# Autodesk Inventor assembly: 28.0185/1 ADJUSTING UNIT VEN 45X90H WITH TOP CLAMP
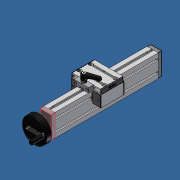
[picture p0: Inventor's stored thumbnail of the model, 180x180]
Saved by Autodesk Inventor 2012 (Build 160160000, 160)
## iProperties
Created: 2007-06
Part Number: 28.0185/1 ADJUSTING UNIT VEN 45X90H WITH TOP CLAMP
Document SubType Name: Assembly
Designer: Andy Moles
Author: Andy Moles
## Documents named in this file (21)
- C:\Andys Backup Data\ANDY'S INVENTOR\INVENTOR LIBRARIES\PARTS LIBRARY\READY FOR USE MODULES LG\28.0185_1 ADJUSTING UNIT VEN 45X90H WITH TOP CLAMP.iam
- C:\Andys Backup Data\ANDY'S INVENTOR\INVENTOR LIBRARIES\PARTS LIBRARY\READY FOR USE MODULES LG\SUBCOMPONENTS\50.1264 BALL BEARING 10X30X9 6200 2RS DIN 625.ipt
- C:\Andys Backup Data\ANDY'S INVENTOR\INVENTOR LIBRARIES\PARTS LIBRARY\READY FOR USE MODULES LG\SUBCOMPONENTS\28.0201 BEARING PLATE 45X90 IDLER SIDE.ipt
- C:\Andys Backup Data\ANDY'S INVENTOR\INVENTOR LIBRARIES\PARTS LIBRARY\READY FOR USE MODULES LG\SUBCOMPONENTS\28.0200 BEARING PLATE 45X90 HANDWHEEL SIDE.ipt
- C:\Andys Backup Data\ANDY'S INVENTOR\INVENTOR LIBRARIES\PARTS LIBRARY\READY FOR USE MODULES LG\SUBCOMPONENTS\28.0204 HANDWHEEL 100mm.iam
- C:\Andys Backup Data\ANDY'S INVENTOR\INVENTOR LIBRARIES\PARTS LIBRARY\FASTENING ELEMENTS\NUTS\21.1351 M8 SQUARE NUT.ipt
- C:\Andys Backup Data\ANDY'S INVENTOR\INVENTOR LIBRARIES\PARTS LIBRARY\FASTENING ELEMENTS\SCREWS CAP\21.1204 M8X25.ipt
- C:\Andys Backup Data\ANDY'S INVENTOR\INVENTOR LIBRARIES\PARTS LIBRARY\READY FOR USE MODULES LG\SUBCOMPONENTS\28.0221_1 ACME SCREW 16X4 TOP LOCK.ipt
- C:\Andys Backup Data\ANDY'S INVENTOR\INVENTOR LIBRARIES\PARTS LIBRARY\FASTENING ELEMENTS\WASHERS\21.1326 DISC SPRING 20.ipt
- C:\Andys Backup Data\ANDY'S INVENTOR\INVENTOR LIBRARIES\PARTS LIBRARY\READY FOR USE MODULES LG\SUBCOMPONENTS\28.0214_3 RAIL 45X90 H PROFILE TOP LOCK.ipt
- C:\Andys Backup Data\ANDY'S INVENTOR\INVENTOR LIBRARIES\PARTS LIBRARY\READY FOR USE MODULES LG\SUBCOMPONENTS\28.0222_1 LWN 32X45-45 90X19-NSC.ipt
- 28.0222/1 SLIDE LWN 32X45-45 90X19.ipt
- C:\Andys Backup Data\ANDY'S INVENTOR\INVENTOR LIBRARIES\PARTS LIBRARY\READY FOR USE MODULES LG\SUBCOMPONENTS\28.0126 SLIDE 45X32.ipt
- C:\Andys Backup Data\ANDY'S INVENTOR\INVENTOR LIBRARIES\PARTS LIBRARY\READY FOR USE MODULES LG\SUBCOMPONENTS\28.0256 Nut slide connector 38.5.ipt
- C:\Andys Backup Data\ANDY'S INVENTOR\INVENTOR LIBRARIES\PARTS LIBRARY\FASTENING ELEMENTS\SCREWS CAP\21.1200 M8X16.ipt
- C:\Andys Backup Data\ANDY'S INVENTOR\INVENTOR LIBRARIES\PARTS LIBRARY\FASTENING ELEMENTS\SCREWS CAP\21.1235 M5X16.ipt
- C:\Andys Backup Data\ANDY'S INVENTOR\INVENTOR LIBRARIES\PARTS LIBRARY\COMPONENTS LR\28.0270_9 SLIDE CLAMPING UNIT 5mm OFFSET..iam
- C:\Andys Backup Data\ANDY'S INVENTOR\INVENTOR LIBRARIES\PARTS LIBRARY\COMPONENTS LG\22.1095 SLIDE RAIL LN.iam
- C:\Andys Backup Data\ANDY'S INVENTOR\INVENTOR LIBRARIES\PARTS LIBRARY\END CAPS\22.1003_1 END CAP 45x32 Z Gray.iam
- C:\Andys Backup Data\ANDY'S INVENTOR\INVENTOR LIBRARIES\PARTS LIBRARY\END CAPS\22.1014_1 END CAP 90X19 GRAY.ipt
- C:\Andys Backup Data\ANDY'S INVENTOR\INVENTOR LIBRARIES\PARTS LIBRARY\READY FOR USE MODULES LG\SUBCOMPONENTS\28.0257 BRONZE NUT 16X4 NOTCHED.ipt
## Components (37 placed, 19 different names)
1. 28.0214_3 RAIL 45X90 H PROFILE TOP LOCK:1 — Mate:1, Flush:1, Mate:2, Mate:6, Angle:3, Flush:3, Mate:21, Flush:4, Flush:5, Flush:6, Flush:7, Angle:16, Mate:38, Mate:39
2. 50.1264 10X30X9 6200 2RS DIN 625 BALL BEARING:1 — Insert:10, Insert:13
3. 50.1264 10X30X9 6200 2RS DIN 625 BALL BEARING:2 — Insert:9
4. 28.0201 BEARING PLATE 45X90 IDLER SIDE:1 — Mate:6, Insert:7, Insert:8, Insert:9, Angle:3, Flush:6, Flush:7
5. 28.0200 BEARING PLATE 45X90 HANDWHEEL SIDE:1 — Insert:3, Insert:5, Insert:6, Insert:10, Flush:3, Mate:21, Flush:4, Flush:5, Angle:6, Angle:18
6. 28.0204 HANDWHEEL 100mm:1 [sub-assembly] — Insert:3, Angle:5, Angle:6
7. 21.1204  M8 x 25:1 — Insert:5
8. 21.1204  M8 x 25:2 — Insert:6
9. 21.1204  M8 x 25:3 — Insert:7
10. 21.1204  M8 x 25:4 — Insert:8
11. 28.0221_1 ACME SCREW 16X4 TOP LOCK:1 — Insert:11, Insert:12, Angle:5, Mate:36
12. 21.1326 DISC SPRING 20:1 — Insert:11, Insert:13
13. 21.1326 DISC SPRING 20:2 — Insert:12
14. 28.0222\1 SLIDE LWN 32X45-45 90X19:1 — Insert:14, Insert:15, Insert:16, Insert:17, Insert:18, Insert:19, Insert:20, Insert:21, Insert:22, Insert:23, Angle:7, Angle:8, Angle:9, Angle:10, Insert:24, Angle:11, Mate:26, Flush:8, Mate:27, Flush:9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
15. 28.0126 SLIDE 45X32:1 — Mate:27, Flush:9, Flush:10, Mate:30, Flush:13, Mate:31, Insert:25, Insert:28, Angle:13, Angle:17
16. 28.0126 SLIDE 45X32:2 — Mate:26, Flush:8, Flush:11, Mate:32, Flush:14, Mate:33, Insert:26, Insert:27, Angle:14, Angle:15
17. 28.0256 Nut slide connector 38.5:1 — Insert:24, Angle:11, Mate:37, Mate:40
18. 21.1200 M8 x 16:1 — Insert:16
19. 21.1200 M8 x 16:2 — Insert:17
20. 21.1200 M8 x 16:3 — Insert:18
21. 21.1200 M8 x 16:4 — Insert:19
22. 21.1235  M5 x 16:1 — Insert:15
23. 21.1235  M5 x 16:2 — Insert:14
24. 21.1351 M8 SQUARE NUT:2 — Insert:21, Angle:10
25. 21.1351 M8 SQUARE NUT:3 — Insert:22, Angle:7
26. 21.1351 M8 SQUARE NUT:4 — Insert:23, Angle:8
27. 21.1351 M8 SQUARE NUT:5 — Insert:20, Angle:9
28. 28.0270_9 SLIDE CLAMPING UNIT 5mm OFFSET.:1 [sub-assembly] — Mate:28, Angle:12, Flush:12, Mate:29
29. 22.1095 SLIDE RAIL LN:1 [sub-assembly] — Mate:30, Flush:13, Mate:31
30. 22.1095 SLIDE RAIL LN:2 [sub-assembly] — Mate:32, Flush:14, Mate:33, Mate:38, Mate:39
31. 22.1003\1 END CAP 45x32 Z Gray:1 [sub-assembly] — Insert:25, Angle:17
32. 22.1003\1 END CAP 45x32 Z Gray:2 [sub-assembly] — Insert:26, Angle:15
33. 22.1003\1 END CAP 45x32 Z Gray:3 [sub-assembly] — Insert:27, Angle:14
34. 22.1003\1 END CAP 45x32 Z Gray:4 [sub-assembly] — Insert:28, Angle:13
35. 22.1014_1 END CAP 90X19 GRAY:1 — Mate:34, Flush:15, Flush:16
36. 22.1014_1 END CAP 90X19 GRAY:2 — Mate:35, Flush:17, Flush:18
37. 28.0257 BRONZE NUT 16X4 NOTCHED:1 — Mate:36, Mate:37, Mate:40
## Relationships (76: Insert 25, Mate 19, Flush 17, Angle 15)
- Mate:1: 28.0214_3 RAIL 45X90 H PROFILE TOP LOCK:1
- Flush:1: 28.0214_3 RAIL 45X90 H PROFILE TOP LOCK:1
- Mate:2: 28.0214_3 RAIL 45X90 H PROFILE TOP LOCK:1
- Mate:6: 28.0214_3 RAIL 45X90 H PROFILE TOP LOCK:1 ↔ 28.0201 BEARING PLATE 45X90 IDLER SIDE:1
- Insert:3: 28.0200 BEARING PLATE 45X90 HANDWHEEL SIDE:1 ↔ 28.0204 HANDWHEEL 100mm:1
- Insert:5: 28.0200 BEARING PLATE 45X90 HANDWHEEL SIDE:1 ↔ 21.1204  M8 x 25:1
- Insert:6: 28.0200 BEARING PLATE 45X90 HANDWHEEL SIDE:1 ↔ 21.1204  M8 x 25:2
- Insert:7: 28.0201 BEARING PLATE 45X90 IDLER SIDE:1 ↔ 21.1204  M8 x 25:3
- Insert:8: 28.0201 BEARING PLATE 45X90 IDLER SIDE:1 ↔ 21.1204  M8 x 25:4
- Insert:9: 50.1264 10X30X9 6200 2RS DIN 625 BALL BEARING:2 ↔ 28.0201 BEARING PLATE 45X90 IDLER SIDE:1
- Insert:10: 50.1264 10X30X9 6200 2RS DIN 625 BALL BEARING:1 ↔ 28.0200 BEARING PLATE 45X90 HANDWHEEL SIDE:1
- Angle:3: 28.0214_3 RAIL 45X90 H PROFILE TOP LOCK:1 ↔ 28.0201 BEARING PLATE 45X90 IDLER SIDE:1
- Flush:3: 28.0214_3 RAIL 45X90 H PROFILE TOP LOCK:1 ↔ 28.0200 BEARING PLATE 45X90 HANDWHEEL SIDE:1
- Mate:21: 28.0214_3 RAIL 45X90 H PROFILE TOP LOCK:1 ↔ 28.0200 BEARING PLATE 45X90 HANDWHEEL SIDE:1
- Flush:4: 28.0214_3 RAIL 45X90 H PROFILE TOP LOCK:1 ↔ 28.0200 BEARING PLATE 45X90 HANDWHEEL SIDE:1
- Flush:5: 28.0214_3 RAIL 45X90 H PROFILE TOP LOCK:1 ↔ 28.0200 BEARING PLATE 45X90 HANDWHEEL SIDE:1
- Flush:6: 28.0214_3 RAIL 45X90 H PROFILE TOP LOCK:1 ↔ 28.0201 BEARING PLATE 45X90 IDLER SIDE:1
- Flush:7: 28.0214_3 RAIL 45X90 H PROFILE TOP LOCK:1 ↔ 28.0201 BEARING PLATE 45X90 IDLER SIDE:1
- Insert:11: 28.0221_1 ACME SCREW 16X4 TOP LOCK:1 ↔ 21.1326 DISC SPRING 20:1
- Insert:12: 28.0221_1 ACME SCREW 16X4 TOP LOCK:1 ↔ 21.1326 DISC SPRING 20:2
- Insert:13: 50.1264 10X30X9 6200 2RS DIN 625 BALL BEARING:1 ↔ 21.1326 DISC SPRING 20:1
- Angle:5: 28.0204 HANDWHEEL 100mm:1 ↔ 28.0221_1 ACME SCREW 16X4 TOP LOCK:1
- Angle:6: 28.0200 BEARING PLATE 45X90 HANDWHEEL SIDE:1 ↔ 28.0204 HANDWHEEL 100mm:1
- Insert:14: 28.0222\1 SLIDE LWN 32X45-45 90X19:1 ↔ 21.1235  M5 x 16:2
- Insert:15: 28.0222\1 SLIDE LWN 32X45-45 90X19:1 ↔ 21.1235  M5 x 16:1
- Insert:16: 28.0222\1 SLIDE LWN 32X45-45 90X19:1 ↔ 21.1200 M8 x 16:1
- Insert:17: 28.0222\1 SLIDE LWN 32X45-45 90X19:1 ↔ 21.1200 M8 x 16:2
- Insert:18: 28.0222\1 SLIDE LWN 32X45-45 90X19:1 ↔ 21.1200 M8 x 16:3
- Insert:19: 28.0222\1 SLIDE LWN 32X45-45 90X19:1 ↔ 21.1200 M8 x 16:4
- Insert:20: 28.0222\1 SLIDE LWN 32X45-45 90X19:1 ↔ 21.1351 M8 SQUARE NUT:5
- Insert:21: 28.0222\1 SLIDE LWN 32X45-45 90X19:1 ↔ 21.1351 M8 SQUARE NUT:2
- Insert:22: 28.0222\1 SLIDE LWN 32X45-45 90X19:1 ↔ 21.1351 M8 SQUARE NUT:3
- Insert:23: 28.0222\1 SLIDE LWN 32X45-45 90X19:1 ↔ 21.1351 M8 SQUARE NUT:4
- Angle:7: 28.0222\1 SLIDE LWN 32X45-45 90X19:1 ↔ 21.1351 M8 SQUARE NUT:3
- Angle:8: 28.0222\1 SLIDE LWN 32X45-45 90X19:1 ↔ 21.1351 M8 SQUARE NUT:4
- Angle:9: 28.0222\1 SLIDE LWN 32X45-45 90X19:1 ↔ 21.1351 M8 SQUARE NUT:5
- Angle:10: 28.0222\1 SLIDE LWN 32X45-45 90X19:1 ↔ 21.1351 M8 SQUARE NUT:2
- Insert:24: 28.0222\1 SLIDE LWN 32X45-45 90X19:1 ↔ 28.0256 Nut slide connector 38.5:1
- Angle:11: 28.0222\1 SLIDE LWN 32X45-45 90X19:1 ↔ 28.0256 Nut slide connector 38.5:1
- Mate:26: 28.0222\1 SLIDE LWN 32X45-45 90X19:1 ↔ 28.0126 SLIDE 45X32:2
- Flush:8: 28.0222\1 SLIDE LWN 32X45-45 90X19:1 ↔ 28.0126 SLIDE 45X32:2
- Mate:27: 28.0222\1 SLIDE LWN 32X45-45 90X19:1 ↔ 28.0126 SLIDE 45X32:1
- Flush:9: 28.0222\1 SLIDE LWN 32X45-45 90X19:1 ↔ 28.0126 SLIDE 45X32:1
- Flush:10: 28.0222\1 SLIDE LWN 32X45-45 90X19:1 ↔ 28.0126 SLIDE 45X32:1
- Flush:11: 28.0222\1 SLIDE LWN 32X45-45 90X19:1 ↔ 28.0126 SLIDE 45X32:2
- Mate:28: 28.0222\1 SLIDE LWN 32X45-45 90X19:1 ↔ 28.0270_9 SLIDE CLAMPING UNIT 5mm OFFSET.:1
- Angle:12: 28.0222\1 SLIDE LWN 32X45-45 90X19:1 ↔ 28.0270_9 SLIDE CLAMPING UNIT 5mm OFFSET.:1
- Flush:12: 28.0222\1 SLIDE LWN 32X45-45 90X19:1 ↔ 28.0270_9 SLIDE CLAMPING UNIT 5mm OFFSET.:1
- Mate:29: 28.0222\1 SLIDE LWN 32X45-45 90X19:1 ↔ 28.0270_9 SLIDE CLAMPING UNIT 5mm OFFSET.:1
- Mate:30: 28.0126 SLIDE 45X32:1 ↔ 22.1095 SLIDE RAIL LN:1
- Flush:13: 28.0126 SLIDE 45X32:1 ↔ 22.1095 SLIDE RAIL LN:1
- Mate:31: 28.0126 SLIDE 45X32:1 ↔ 22.1095 SLIDE RAIL LN:1
- Mate:32: 28.0126 SLIDE 45X32:2 ↔ 22.1095 SLIDE RAIL LN:2
- Flush:14: 28.0126 SLIDE 45X32:2 ↔ 22.1095 SLIDE RAIL LN:2
- Mate:33: 28.0126 SLIDE 45X32:2 ↔ 22.1095 SLIDE RAIL LN:2
- Insert:25: 28.0126 SLIDE 45X32:1 ↔ 22.1003\1 END CAP 45x32 Z Gray:1
- Insert:26: 28.0126 SLIDE 45X32:2 ↔ 22.1003\1 END CAP 45x32 Z Gray:2
- Insert:27: 28.0126 SLIDE 45X32:2 ↔ 22.1003\1 END CAP 45x32 Z Gray:3
- Insert:28: 28.0126 SLIDE 45X32:1 ↔ 22.1003\1 END CAP 45x32 Z Gray:4
- Angle:13: 28.0126 SLIDE 45X32:1 ↔ 22.1003\1 END CAP 45x32 Z Gray:4
- Angle:14: 28.0126 SLIDE 45X32:2 ↔ 22.1003\1 END CAP 45x32 Z Gray:3
- Angle:15: 28.0126 SLIDE 45X32:2 ↔ 22.1003\1 END CAP 45x32 Z Gray:2
- Mate:34: 28.0222\1 SLIDE LWN 32X45-45 90X19:1 ↔ 22.1014_1 END CAP 90X19 GRAY:1
- Flush:15: 28.0222\1 SLIDE LWN 32X45-45 90X19:1 ↔ 22.1014_1 END CAP 90X19 GRAY:1
- Flush:16: 28.0222\1 SLIDE LWN 32X45-45 90X19:1 ↔ 22.1014_1 END CAP 90X19 GRAY:1
- Mate:35: 28.0222\1 SLIDE LWN 32X45-45 90X19:1 ↔ 22.1014_1 END CAP 90X19 GRAY:2
- Flush:17: 28.0222\1 SLIDE LWN 32X45-45 90X19:1 ↔ 22.1014_1 END CAP 90X19 GRAY:2
- Flush:18: 28.0222\1 SLIDE LWN 32X45-45 90X19:1 ↔ 22.1014_1 END CAP 90X19 GRAY:2
- Angle:16: 28.0214_3 RAIL 45X90 H PROFILE TOP LOCK:1 ↔ 28.0222\1 SLIDE LWN 32X45-45 90X19:1
- Angle:17: 28.0126 SLIDE 45X32:1 ↔ 22.1003\1 END CAP 45x32 Z Gray:1
- Angle:18: 28.0200 BEARING PLATE 45X90 HANDWHEEL SIDE:1 ↔ 28.0222\1 SLIDE LWN 32X45-45 90X19:1
- Mate:36: 28.0221_1 ACME SCREW 16X4 TOP LOCK:1 ↔ 28.0257 BRONZE NUT 16X4 NOTCHED:1
- Mate:37: 28.0256 Nut slide connector 38.5:1 ↔ 28.0257 BRONZE NUT 16X4 NOTCHED:1
- Mate:38: 28.0214_3 RAIL 45X90 H PROFILE TOP LOCK:1 ↔ 22.1095 SLIDE RAIL LN:2
- Mate:39: 28.0214_3 RAIL 45X90 H PROFILE TOP LOCK:1 ↔ 22.1095 SLIDE RAIL LN:2
- Mate:40: 28.0256 Nut slide connector 38.5:1 ↔ 28.0257 BRONZE NUT 16X4 NOTCHED:1
